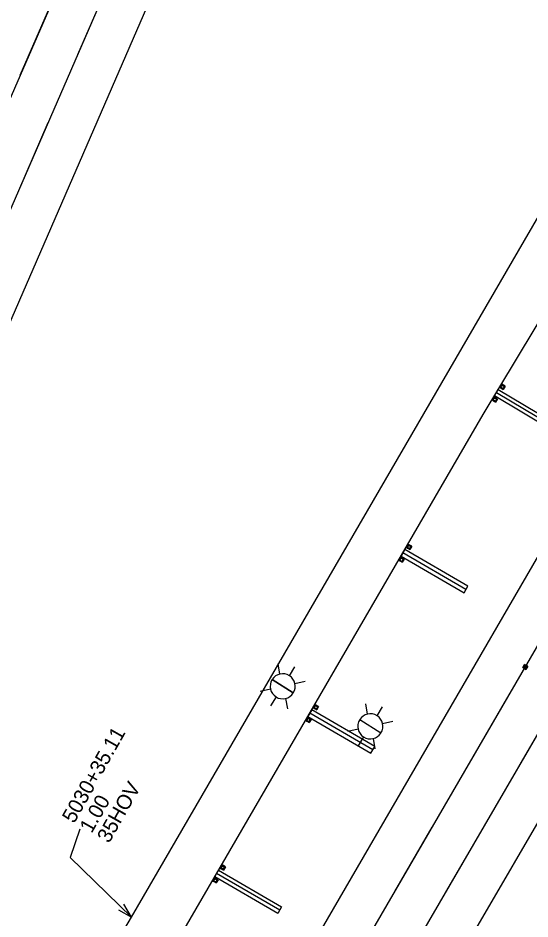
# Model space of a CAD drawing. Extents: x 2471014 to 2497726, y 6959577 to 6980268.
# Drawn here: x 2488611.6 to 2488749.7, y 6964391.9 to 6964634.8 of the extents above; entities that cross this region are included whole.
import ezdxf

# ---------------------------------------------------------------- set-up
doc = ezdxf.new("R2010")
doc.units = 0
for name, color, linetype in [('13', 7, 'Continuous'), ('18', 7, 'Continuous'), ('23', 7, 'Continuous'), ('25', 7, 'Continuous'), ('G-GRID-MAJR', 7, 'Continuous'), ('PMK_Del_D-SW_SZ_TYC_CTB_BI', 7, 'Continuous'), ('PMK_Pav_Marker_TY I C', 7, 'Continuous'), ('RDWY_PAVE_XSTREET_FOC', 7, 'Continuous'), ('S-BRDG-BENT', 7, 'Continuous'), ('S-BRDG-DECK', 7, 'Continuous'), ('V7_25', 7, 'Continuous')]:
    doc.layers.add(name, color=color, linetype=linetype)

msp = doc.modelspace()

# ---------------------------------------------------------------- linework, layer by layer
at = {"layer": '13'}
for p, q in [((2488516.12, 6964338.68), (2489359.15, 6966274.8)), ((2488620.75, 6964263.98), (2489501.89, 6965780.24))]:
    msp.add_line(p, q, dxfattribs=at)
at = {"layer": '18'}
for p, q in [((2488642.18, 6964392.39), (2489501.29, 6965870.76)), ((2488735.14, 6964389.16), (2489533.02, 6965762.15)), ((2488737.13, 6964527.93), (2489107.54, 6965145.42)), ((2488654.28, 6964385.36), (2488737.13, 6964527.93)), ((2488581.52, 6964289.01), (2488642.18, 6964392.39))]:
    msp.add_line(p, q, dxfattribs=at)
msp.add_arc((2484366.43, 6966145.55), 4460, 338.95644, 344.32475, dxfattribs=at)
at = {"layer": '23'}
for p, q in [((2488747.77, 6964459.65), (2488748.28, 6964460.52)), ((2488747.99, 6964459.71), (2488747.77, 6964459.65)), ((2488747.77, 6964459.65), (2488748, 6964459.51)), ((2488748.57, 6964459.37), (2488747.99, 6964459.71)), ((2488748, 6964459.51), (2488748.64, 6964459.14)), ((2488749.15, 6964460.01), (2488748.28, 6964460.52)), ((2488748.28, 6964460.52), (2488748.33, 6964460.3)), ((2488748.33, 6964460.3), (2488748.45, 6964460.22)), ((2488748.45, 6964460.22), (2488748.91, 6964459.96)), ((2488748.64, 6964459.14), (2488748.57, 6964459.37)), ((2488749.15, 6964460.01), (2488748.64, 6964459.14)), ((2488748.91, 6964459.96), (2488749.15, 6964460.01))]:
    msp.add_line(p, q, dxfattribs=at)
msp.add_lwpolyline([(2488747.99, 6964459.71), (2488748.33, 6964460.3), (2488748.91, 6964459.96), (2488748.57, 6964459.37)], close=True, dxfattribs=at)
at = {"layer": '25'}
for centre, radius, start, end in [((2484366.43, 6966145.55), 4474, 338.50023, 342.56518), ((2485597.1, 6966838.82), 4024, 321.30547, 324.04653)]:
    msp.add_arc(centre, radius, start, end, dxfattribs=at)
at = {"layer": 'G-GRID-MAJR'}
for p, q in [((2488740.13, 6964532.93), (2488741.16, 6964534.64)), ((2488741.16, 6964534.64), (2488757.94, 6964524.57)), ((2488756.91, 6964522.86), (2488740.13, 6964532.93)), ((2488715.94, 6964491.47), (2488714.94, 6964489.74)), ((2488732.95, 6964481.58), (2488715.94, 6964491.47)), ((2488714.94, 6964489.74), (2488731.94, 6964479.86)), ((2488731.94, 6964479.86), (2488732.95, 6964481.58)), ((2488690.82, 6964448.24), (2488689.81, 6964446.51)), ((2488707.82, 6964438.35), (2488690.82, 6964448.24)), ((2488689.81, 6964446.51), (2488706.82, 6964436.62)), ((2488706.82, 6964436.62), (2488707.82, 6964438.35)), ((2488664.69, 6964403.28), (2488665.7, 6964405)), ((2488681.7, 6964393.39), (2488664.69, 6964403.28)), ((2488665.7, 6964405), (2488682.7, 6964395.12)), ((2488682.7, 6964395.12), (2488681.7, 6964393.39))]:
    msp.add_line(p, q, dxfattribs=at)
at = {"layer": 'PMK_Del_D-SW_SZ_TYC_CTB_BI'}
for p, q in [((2488682.26, 6964457.92), (2488681.74, 6964460.68)), ((2488684.81, 6964457.48), (2488686.31, 6964459.86)), ((2488685.85, 6964452.81), (2488680.14, 6964456.41)), ((2488680.15, 6964456.43), (2488685.86, 6964452.83)), ((2488686.3, 6964455.37), (2488689.03, 6964456.03)), ((2488679.7, 6964453.87), (2488676.97, 6964453.21)), ((2488681.2, 6964451.76), (2488679.7, 6964449.38)), ((2488683.74, 6964451.32), (2488684.26, 6964448.55)), ((2488705.91, 6964447.12), (2488705.39, 6964449.89)), ((2488708.45, 6964446.69), (2488709.95, 6964449.06)), ((2488709.5, 6964442.01), (2488703.79, 6964445.61)), ((2488703.8, 6964445.63), (2488709.51, 6964442.03)), ((2488709.94, 6964444.58), (2488712.68, 6964445.24)), ((2488703.35, 6964443.07), (2488700.62, 6964442.41)), ((2488704.84, 6964440.96), (2488703.34, 6964438.58)), ((2488707.39, 6964440.52), (2488707.9, 6964437.76))]:
    msp.add_line(p, q, dxfattribs=at)
for centre, start, end in [((2488683.01, 6964454.63), 327.7622, 147.7622), ((2488683, 6964454.61), 147.7622, 327.7622), ((2488706.65, 6964443.83), 327.7622, 147.7622), ((2488706.64, 6964443.81), 147.7622, 327.7622)]:
    msp.add_arc(centre, 3.37, start, end, dxfattribs=at)
at = {"layer": 'PMK_Pav_Marker_TY I C'}
for p, q in [((2488741.64, 6964535.2), (2488742.16, 6964536.07)), ((2488741.86, 6964535.26), (2488741.64, 6964535.2)), ((2488741.64, 6964535.2), (2488741.87, 6964535.06)), ((2488742.44, 6964534.91), (2488741.86, 6964535.26)), ((2488741.87, 6964535.06), (2488742.51, 6964534.68)), ((2488743.03, 6964535.55), (2488742.16, 6964536.07)), ((2488742.16, 6964536.07), (2488742.21, 6964535.84)), ((2488742.21, 6964535.84), (2488742.33, 6964535.77)), ((2488742.33, 6964535.77), (2488742.79, 6964535.49)), ((2488742.51, 6964534.68), (2488742.44, 6964534.91)), ((2488743.03, 6964535.55), (2488742.51, 6964534.68)), ((2488742.79, 6964535.49), (2488743.03, 6964535.55)), ((2488739.58, 6964531.77), (2488740.11, 6964532.64)), ((2488740.97, 6964532.11), (2488740.11, 6964532.64)), ((2488740.11, 6964532.64), (2488740.15, 6964532.41)), ((2488740.15, 6964532.41), (2488740.28, 6964532.34)), ((2488740.28, 6964532.34), (2488740.74, 6964532.06)), ((2488740.97, 6964532.11), (2488740.45, 6964531.25)), ((2488740.74, 6964532.06), (2488740.97, 6964532.11)), ((2488739.81, 6964531.83), (2488739.58, 6964531.77)), ((2488739.58, 6964531.77), (2488739.82, 6964531.63)), ((2488740.39, 6964531.48), (2488739.81, 6964531.83)), ((2488739.82, 6964531.63), (2488740.45, 6964531.25)), ((2488740.45, 6964531.25), (2488740.39, 6964531.48)), ((2488716.42, 6964492.02), (2488716.94, 6964492.89)), ((2488716.65, 6964492.08), (2488716.42, 6964492.02)), ((2488716.42, 6964492.02), (2488716.66, 6964491.88)), ((2488717.23, 6964491.74), (2488716.65, 6964492.08)), ((2488716.66, 6964491.88), (2488717.3, 6964491.5)), ((2488717.81, 6964492.38), (2488716.94, 6964492.89)), ((2488716.94, 6964492.89), (2488716.99, 6964492.66)), ((2488716.99, 6964492.66), (2488717.11, 6964492.59)), ((2488717.11, 6964492.59), (2488717.57, 6964492.32)), ((2488717.3, 6964491.5), (2488717.23, 6964491.74)), ((2488717.81, 6964492.38), (2488717.3, 6964491.5)), ((2488717.57, 6964492.32), (2488717.81, 6964492.38)), ((2488714.39, 6964488.57), (2488714.91, 6964489.45)), ((2488714.61, 6964488.64), (2488714.39, 6964488.57)), ((2488714.39, 6964488.57), (2488714.62, 6964488.44)), ((2488715.2, 6964488.29), (2488714.61, 6964488.64)), ((2488714.62, 6964488.44), (2488715.26, 6964488.06)), ((2488715.78, 6964488.93), (2488714.91, 6964489.45)), ((2488714.91, 6964489.45), (2488714.96, 6964489.22)), ((2488714.96, 6964489.22), (2488715.08, 6964489.15)), ((2488715.08, 6964489.15), (2488715.54, 6964488.88)), ((2488715.26, 6964488.06), (2488715.2, 6964488.29)), ((2488715.78, 6964488.93), (2488715.26, 6964488.06)), ((2488715.54, 6964488.88), (2488715.78, 6964488.93)), ((2488691.31, 6964448.79), (2488691.82, 6964449.66)), ((2488692.69, 6964449.14), (2488691.82, 6964449.66)), ((2488691.82, 6964449.66), (2488691.87, 6964449.43)), ((2488691.87, 6964449.43), (2488691.99, 6964449.36)), ((2488691.99, 6964449.36), (2488692.46, 6964449.09)), ((2488691.53, 6964448.85), (2488691.31, 6964448.79)), ((2488691.31, 6964448.79), (2488691.54, 6964448.65)), ((2488692.11, 6964448.5), (2488691.53, 6964448.85)), ((2488691.54, 6964448.65), (2488692.18, 6964448.27)), ((2488692.18, 6964448.27), (2488692.11, 6964448.5)), ((2488692.69, 6964449.14), (2488692.18, 6964448.27)), ((2488692.46, 6964449.09), (2488692.69, 6964449.14)), ((2488689.27, 6964445.35), (2488689.78, 6964446.22)), ((2488689.49, 6964445.41), (2488689.27, 6964445.35)), ((2488689.27, 6964445.35), (2488689.5, 6964445.21)), ((2488690.07, 6964445.06), (2488689.49, 6964445.41)), ((2488689.5, 6964445.21), (2488690.14, 6964444.83)), ((2488690.65, 6964445.7), (2488689.78, 6964446.22)), ((2488689.78, 6964446.22), (2488689.83, 6964445.99)), ((2488689.83, 6964445.99), (2488689.95, 6964445.92)), ((2488689.95, 6964445.92), (2488690.41, 6964445.65)), ((2488690.14, 6964444.83), (2488690.07, 6964445.06)), ((2488690.65, 6964445.7), (2488690.14, 6964444.83)), ((2488690.41, 6964445.65), (2488690.65, 6964445.7)), ((2488666.16, 6964405.56), (2488666.66, 6964406.44)), ((2488666.38, 6964405.63), (2488666.16, 6964405.56)), ((2488666.16, 6964405.56), (2488666.39, 6964405.43)), ((2488666.97, 6964405.29), (2488666.38, 6964405.63)), ((2488667.54, 6964405.94), (2488666.66, 6964406.44)), ((2488666.66, 6964406.44), (2488666.72, 6964406.21)), ((2488666.72, 6964406.21), (2488666.84, 6964406.14)), ((2488666.84, 6964406.14), (2488667.3, 6964405.88)), ((2488667.54, 6964405.94), (2488667.04, 6964405.06)), ((2488667.3, 6964405.88), (2488667.54, 6964405.94)), ((2488666.39, 6964405.43), (2488667.04, 6964405.06)), ((2488667.04, 6964405.06), (2488666.97, 6964405.29)), ((2488664.17, 6964402.09), (2488664.68, 6964402.97)), ((2488664.4, 6964402.16), (2488664.17, 6964402.09)), ((2488664.17, 6964402.09), (2488664.41, 6964401.96)), ((2488664.98, 6964401.82), (2488664.4, 6964402.16)), ((2488664.41, 6964401.96), (2488665.05, 6964401.59)), ((2488665.56, 6964402.47), (2488664.68, 6964402.97)), ((2488664.68, 6964402.97), (2488664.73, 6964402.74)), ((2488664.73, 6964402.74), (2488664.85, 6964402.67)), ((2488664.85, 6964402.67), (2488665.32, 6964402.41)), ((2488665.05, 6964401.59), (2488664.98, 6964401.82)), ((2488665.56, 6964402.47), (2488665.05, 6964401.59)), ((2488665.32, 6964402.41), (2488665.56, 6964402.47))]:
    msp.add_line(p, q, dxfattribs=at)
for points in [[(2488741.86, 6964535.26), (2488742.21, 6964535.84), (2488742.79, 6964535.49), (2488742.44, 6964534.91)], [(2488739.81, 6964531.83), (2488740.15, 6964532.41), (2488740.74, 6964532.06), (2488740.39, 6964531.48)], [(2488716.65, 6964492.08), (2488716.99, 6964492.66), (2488717.57, 6964492.32), (2488717.23, 6964491.74)], [(2488714.61, 6964488.64), (2488714.96, 6964489.22), (2488715.54, 6964488.88), (2488715.2, 6964488.29)], [(2488691.53, 6964448.85), (2488691.87, 6964449.43), (2488692.46, 6964449.09), (2488692.11, 6964448.5)], [(2488689.49, 6964445.41), (2488689.83, 6964445.99), (2488690.41, 6964445.65), (2488690.07, 6964445.06)], [(2488666.38, 6964405.63), (2488666.72, 6964406.21), (2488667.3, 6964405.88), (2488666.97, 6964405.29)], [(2488664.4, 6964402.16), (2488664.73, 6964402.74), (2488665.32, 6964402.41), (2488664.98, 6964401.82)]]:
    msp.add_lwpolyline(points, close=True, dxfattribs=at)
at = {"layer": 'RDWY_PAVE_XSTREET_FOC'}
for p, q in [((2488635.65, 6964643.25), (2488627.66, 6964624.91)), ((2488620.12, 6964637.64), (2488612.13, 6964619.3)), ((2488619.68, 6964606.57), (2488611.69, 6964588.23)), ((2488733.38, 6964433.9), (2488743.43, 6964451.19)), ((2488747.13, 6964433.68), (2488757.18, 6964450.97)), ((2488713.28, 6964399.31), (2488723.33, 6964416.6)), ((2488727.03, 6964399.1), (2488737.08, 6964416.39))]:
    msp.add_line(p, q, dxfattribs=at)
at = {"layer": 'S-BRDG-BENT'}
for points in [[(2488628.29, 6964416.12), (2488625.69, 6964408.42), (2488642.18, 6964392.39)], [(2488638.68, 6964394.34), (2488642.18, 6964392.39), (2488640.13, 6964395.83)]]:
    msp.add_lwpolyline(points, dxfattribs=at)
at = {"layer": 'S-BRDG-DECK'}
for p, q in [((2488737.13, 6964527.93), (2489107.54, 6965145.42)), ((2488757.43, 6964523.71), (2488740.64, 6964533.78)), ((2488654.27, 6964385.33), (2488737.13, 6964527.93)), ((2488732.44, 6964480.72), (2488715.44, 6964490.6)), ((2488707.32, 6964437.49), (2488690.32, 6964447.37)), ((2488682.2, 6964394.26), (2488665.19, 6964404.14))]:
    msp.add_line(p, q, dxfattribs=at)
at = {"layer": 'V7_25'}
for p, q in [((2489337.14, 6966284.38), (2488494.11, 6964348.26)), ((2489348.15, 6966279.59), (2488505.12, 6964343.47)), ((2488631.13, 6964257.95), (2489512.27, 6965774.21)), ((2488641.5, 6964251.92), (2489522.64, 6965768.18))]:
    msp.add_line(p, q, dxfattribs=at)

# ---------------------------------------------------------------- texts
at = {"layer": 'S-BRDG-BENT'}
for s, p in [('5030+35.11', (2488626.73, 6964417.44)), ('35HOV', (2488636.16, 6964412.1)), ('1.00', (2488631.45, 6964414.77))]:
    msp.add_text(s, height=4, rotation=60.4913, dxfattribs=at).set_placement(p)

doc.saveas('drawing.dxf')
